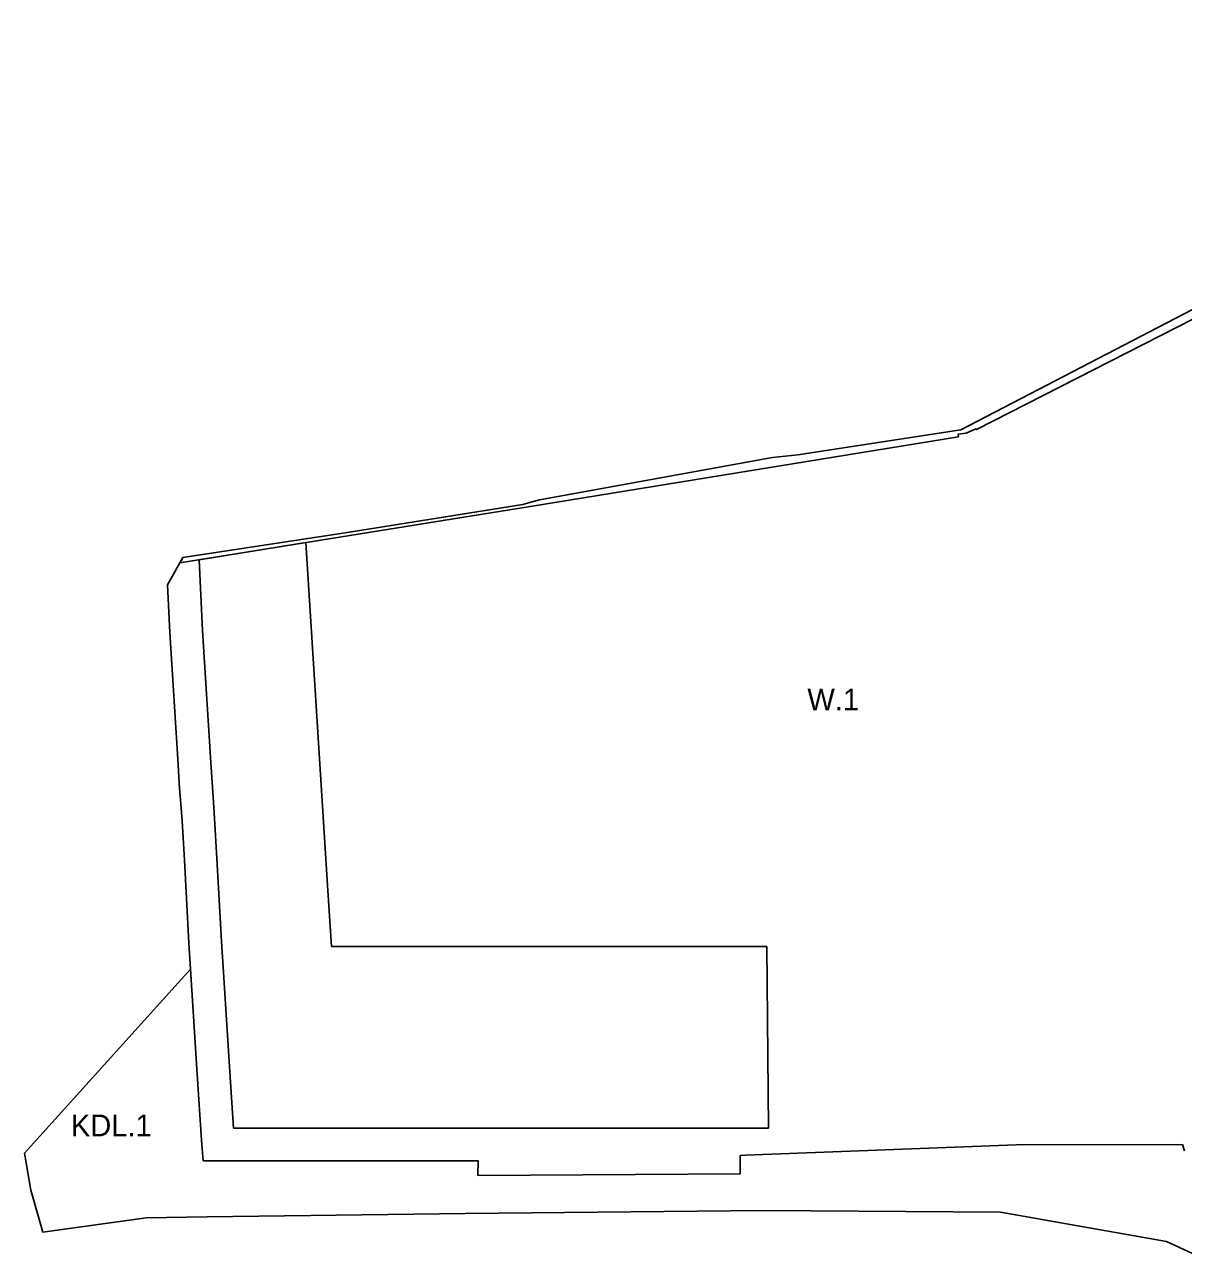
# Model space of a CAD drawing. Extents: x 7432050 to 7433361, y 5551438 to 5552391.
# Drawn here: x 7432049.7 to 7432262.6, y 5551746.4 to 5551973 of the extents above; entities that cross this region are included whole.
import ezdxf

# ---------------------------------------------------------------- set-up
doc = ezdxf.new("R2010")
doc.units = 0
for name, color, linetype in [('granica planu', 7, 'Continuous'), ('linie rozgraniczające', 7, 'Continuous'), ('nieprzekraczalne linie zabudowy', 7, 'Continuous'), ('oznaczenia przeznaczen', 7, 'Continuous')]:
    doc.layers.add(name, color=color, linetype=linetype)

msp = doc.modelspace()

# ---------------------------------------------------------------- linework, layer by layer
at = {"layer": 'granica planu'}
for p, q in [((7432052.96, 5551751.06), (7432050.81, 5551758.78)), ((7432130.63, 5551754.49), (7432083.22, 5551753.85)), ((7432185.43, 5551755.05), (7432130.63, 5551754.49))]:
    msp.add_line(p, q, dxfattribs=at)
for points in [[(7432079, 5551819.42), (7432078.58, 5551826.67), (7432078.04, 5551833.5), (7432077.88, 5551837.01), (7432076.32, 5551861.3), (7432075.92, 5551870.04), (7432078.73, 5551875.08), (7432108.56, 5551879.6), (7432138.53, 5551884.4), (7432141.21, 5551884.83), (7432142.71, 5551885.23), (7432144.25, 5551885.65), (7432187.12, 5551893.44), (7432191.76, 5551893.96), (7432221.7, 5551898.54), (7432302.19, 5551940.32)], [(7432080.14, 5551799.38), (7432079.84, 5551804.15), (7432079, 5551819.42)], [(7432050.81, 5551758.78), (7432049.65, 5551765.54), (7432080.14, 5551799.38)], [(7432083.22, 5551753.85), (7432071.96, 5551753.69), (7432052.96, 5551751.06)], [(7432265.87, 5551746.41), (7432259.5, 5551749.3), (7432229, 5551754.7), (7432185.43, 5551755.05)]]:
    msp.add_lwpolyline(points, dxfattribs=at)
at = {"layer": 'linie rozgraniczające'}
for p, q in [((7432080.14, 5551799.38), (7432081.35, 5551780.11)), ((7432081.35, 5551780.11), (7432082.14, 5551767.98)), ((7432082.14, 5551767.98), (7432082.46, 5551764.18)), ((7432182.14, 5551765.18), (7432231.89, 5551767.07)), ((7432231.89, 5551767.07), (7432262.45, 5551767.16)), ((7432262.45, 5551767.16), (7432262.81, 5551766)), ((7432049.65, 5551765.54), (7432050.81, 5551758.78)), ((7432082.46, 5551764.18), (7432084.79, 5551764.17)), ((7432181.14, 5551765.15), (7432182.14, 5551765.18)), ((7432181.16, 5551761.77), (7432181.14, 5551765.15)), ((7432084.79, 5551764.17), (7432132.99, 5551764.16)), ((7432132.99, 5551764.16), (7432132.97, 5551761.48)), ((7432132.97, 5551761.48), (7432181.16, 5551761.77)), ((7432050.81, 5551758.78), (7432052.96, 5551751.06)), ((7432052.96, 5551751.06), (7432050.81, 5551758.78)), ((7432052.96, 5551751.06), (7432071.96, 5551753.69)), ((7432071.96, 5551753.69), (7432083.22, 5551753.85)), ((7432083.22, 5551753.85), (7432130.63, 5551754.49)), ((7432130.63, 5551754.49), (7432083.22, 5551753.85)), ((7432130.63, 5551754.49), (7432185.43, 5551755.05)), ((7432185.43, 5551755.05), (7432130.63, 5551754.49)), ((7432259.5, 5551749.3), (7432265.87, 5551746.41))]:
    msp.add_line(p, q, dxfattribs=at)
for points in [[(7432368.19, 5551973.04), (7432338.93, 5551957.54), (7432306.94, 5551940.06), (7432306.83, 5551940.37), (7432304.45, 5551939.53), (7432304.52, 5551939.35), (7432224.57, 5551898.58), (7432224.5, 5551898.75), (7432222.71, 5551897.92), (7432221.22, 5551897.74), (7432221.28, 5551897.29), (7432142.19, 5551884.42), (7432078.18, 5551874.1)], [(7432079, 5551819.42), (7432078.58, 5551826.67), (7432078.04, 5551833.5), (7432077.88, 5551837.01), (7432076.32, 5551861.3), (7432075.92, 5551870.04), (7432078.18, 5551874.1), (7432078.73, 5551875.08), (7432108.56, 5551879.6), (7432138.53, 5551884.4), (7432141.21, 5551884.83), (7432142.71, 5551885.23), (7432144.25, 5551885.65), (7432187.12, 5551893.44), (7432191.76, 5551893.96), (7432221.7, 5551898.54), (7432302.19, 5551940.32)], [(7432080.14, 5551799.38), (7432079.84, 5551804.15), (7432079, 5551819.42)], [(7432049.65, 5551765.54), (7432080.14, 5551799.38), (7432049.65, 5551765.54)], [(7432050.81, 5551758.78), (7432049.65, 5551765.54), (7432080.14, 5551799.38)], [(7432083.22, 5551753.85), (7432071.96, 5551753.69), (7432052.96, 5551751.06)], [(7432185.43, 5551755.05), (7432229, 5551754.7), (7432259.5, 5551749.3)], [(7432265.87, 5551746.41), (7432259.5, 5551749.3), (7432229, 5551754.7), (7432185.43, 5551755.05)]]:
    msp.add_lwpolyline(points, dxfattribs=at)
at = {"layer": 'nieprzekraczalne linie zabudowy'}
for p, q in [((7432101.35, 5551877.83), (7432081.71, 5551874.67)), ((7432105.37, 5551813.88), (7432101.35, 5551877.83)), ((7432106.04, 5551803.56), (7432105.37, 5551813.88)), ((7432186.07, 5551803.54), (7432106.04, 5551803.56)), ((7432186.37, 5551770.15), (7432186.07, 5551803.54)), ((7432086.13, 5551799.76), (7432087.34, 5551780.49)), ((7432087.34, 5551780.49), (7432088.01, 5551770.17)), ((7432088.01, 5551770.17), (7432186.37, 5551770.15))]:
    msp.add_line(p, q, dxfattribs=at)
msp.add_lwpolyline([(7432081.71, 5551874.67), (7432082.31, 5551861.63), (7432083.87, 5551837.39), (7432084.33, 5551830.1), (7432084.57, 5551827.08), (7432084.99, 5551819.76), (7432085.83, 5551804.5), (7432086.13, 5551799.76)], dxfattribs=at)

# ---------------------------------------------------------------- texts
at = {"layer": 'oznaczenia przeznaczen'}
for s, p in [('W.1', (7432193.51, 5551846.95)), ('KDL.1', (7432058.14, 5551768.67))]:
    msp.add_text(s, height=4, dxfattribs=at).set_placement(p)

doc.saveas('drawing.dxf')
